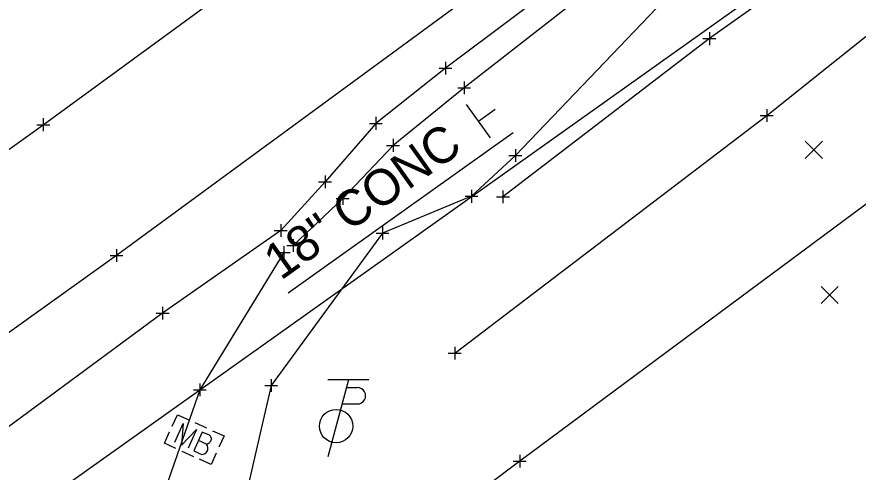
# Model space of a CAD drawing. Extents: x -4 to 139204, y -4 to 477121.
# Drawn here: x 138969.9 to 139035.5, y 476891.5 to 476927 of the extents above; entities that cross this region are included whole.
import ezdxf

# ---------------------------------------------------------------- set-up
doc = ezdxf.new("R2010")
doc.units = 0
for name, color, linetype in [('_CIVIL_CONSTRUCTION', 7, 'Continuous'), ('DR_X_Ditch', 7, 'Continuous'), ('DR_X_Storm_Sewer', 7, 'Continuous'), ('DR_X_Text', 7, 'Continuous'), ('GE_X_Alignment', 7, 'Continuous'), ('GE_X_Alignment_100_Bearings', 7, 'Continuous'), ('GE_X_Alignment_100_Cardinal_Points', 7, 'Continuous'), ('PM_X_Edge_Line', 7, 'Continuous'), ('PM_X_Surveyed_Line', 7, 'Continuous'), ('PV_X_COP', 7, 'Continuous'), ('PV_X_Driveway', 7, 'Continuous'), ('PV_X_EOP', 7, 'Continuous'), ('PV_X_Shoulder', 7, 'Continuous'), ('PV_X_Shoulder_Aggregate', 7, 'Continuous'), ('RD_X_Fence', 7, 'Continuous'), ('RW_X_Esmt_SH', 7, 'Continuous'), ('SC_Scratch1', 7, 'Continuous'), ('UT_X_Gas', 7, 'Continuous')]:
    doc.layers.add(name, color=color, linetype=linetype)

msp = doc.modelspace()

# ---------------------------------------------------------------- linework, layer by layer
at = {"layer": '_CIVIL_CONSTRUCTION'}
for p, q in [((139006.856, 476917.53), (139004.992, 476920.132)), ((139005.924, 476918.831), (139007.225, 476919.763))]:
    msp.add_line(p, q, dxfattribs=at)
at = {"layer": 'DR_X_Ditch'}
msp.add_lwpolyline([(139084.31, 476969.071), (139079.627, 476963.915), (139073.397, 476959.844), (139063.705, 476954.01), (139045.774, 476940.83), (139023.925, 476925.276), (139007.837, 476912.933)], dxfattribs=at)
at = {"layer": 'DR_X_Storm_Sewer'}
msp.add_line((138907.351, 476843.166), (139091.624, 476974.362), dxfattribs=at)
msp.add_line((138907.351, 476843.166), (139091.624, 476974.362), dxfattribs=at)
at = {"layer": 'DR_X_Text'}
msp.add_line((139008.637, 476917.918), (138991.102, 476905.433), dxfattribs=at)
msp.add_line((139008.637, 476917.918), (138991.102, 476905.433), dxfattribs=at)
at = {"layer": 'GE_X_Alignment'}
for p, q in [((139031.4, 476915.928), (139032.734, 476917.264)), ((139031.4, 476917.264), (139032.734, 476915.928)), ((139032.624, 476904.609), (139033.958, 476905.944)), ((139032.624, 476905.944), (139033.958, 476904.609))]:
    msp.add_line(p, q, dxfattribs=at)
at = {"layer": 'GE_X_Alignment_100_Bearings'}
for p, q in [((139023.925, 476925.776), (139023.925, 476924.776)), ((139023.425, 476925.276), (139024.425, 476925.276)), ((139023.925, 476925.276), (139023.925, 476925.276)), ((139002.851, 476922.965), (139003.851, 476922.965)), ((139003.351, 476923.465), (139003.351, 476922.465)), ((139003.351, 476922.965), (139003.351, 476922.965)), ((139004.817, 476921.929), (139004.817, 476920.929)), ((139004.317, 476921.429), (139005.317, 476921.429)), ((139004.817, 476921.429), (139004.817, 476921.429)), ((139028.392, 476919.779), (139028.392, 476918.779)), ((138972.007, 476919.062), (138972.007, 476918.062)), ((138972.007, 476919.062), (138972.007, 476918.062)), ((138997.924, 476919.166), (138997.924, 476918.166)), ((139027.892, 476919.279), (139028.892, 476919.279)), ((139028.392, 476919.279), (139028.392, 476919.279)), ((138971.507, 476918.562), (138972.507, 476918.562)), ((138971.507, 476918.562), (138972.507, 476918.562)), ((138972.007, 476918.562), (138972.007, 476918.562)), ((138972.007, 476918.562), (138972.007, 476918.562)), ((138997.424, 476918.666), (138998.424, 476918.666)), ((138997.924, 476918.666), (138997.924, 476918.666)), ((138999.267, 476917.449), (138999.267, 476916.449)), ((138998.767, 476916.949), (138999.767, 476916.949)), ((138999.267, 476916.949), (138999.267, 476916.949)), ((139008.806, 476916.658), (139008.806, 476915.658)), ((139008.306, 476916.158), (139009.306, 476916.158)), ((139008.806, 476916.158), (139008.806, 476916.158)), ((138993.965, 476914.598), (138993.965, 476913.598)), ((138993.465, 476914.098), (138994.465, 476914.098)), ((138993.965, 476914.098), (138993.965, 476914.098)), ((138995.343, 476913.315), (138995.343, 476912.315)), ((139005.384, 476913.478), (139005.384, 476912.478)), ((139007.837, 476913.433), (139007.837, 476912.433)), ((138994.843, 476912.815), (138995.843, 476912.815)), ((138995.343, 476912.815), (138995.343, 476912.815)), ((139004.884, 476912.978), (139005.884, 476912.978)), ((139005.384, 476912.978), (139005.384, 476912.978)), ((139007.337, 476912.933), (139008.337, 476912.933)), ((139007.837, 476912.933), (139007.837, 476912.933)), ((138990.512, 476910.809), (138990.512, 476909.809)), ((138998.45, 476910.612), (138998.45, 476909.612)), ((138990.012, 476910.309), (138991.012, 476910.309)), ((138990.512, 476910.309), (138990.512, 476910.309)), ((138997.95, 476910.112), (138998.95, 476910.112)), ((138998.45, 476910.112), (138998.45, 476910.112)), ((138990.994, 476909.144), (138991.994, 476909.144)), ((138991.494, 476909.644), (138991.494, 476908.644)), ((138991.494, 476909.144), (138991.494, 476909.144)), ((138977.717, 476908.855), (138977.717, 476907.855)), ((138977.717, 476908.855), (138977.717, 476907.855)), ((138990.254, 476908.584), (138991.254, 476908.584)), ((138990.754, 476909.084), (138990.754, 476908.084)), ((138990.754, 476908.584), (138990.754, 476908.584)), ((138977.217, 476908.355), (138978.217, 476908.355)), ((138977.217, 476908.355), (138978.217, 476908.355)), ((138977.717, 476908.355), (138977.717, 476908.355)), ((138977.717, 476908.355), (138977.717, 476908.355)), ((138981.306, 476904.356), (138981.306, 476903.356)), ((138980.806, 476903.856), (138981.806, 476903.856)), ((138981.306, 476903.856), (138981.306, 476903.856)), ((139003.575, 476900.734), (139004.575, 476900.734)), ((139004.075, 476901.234), (139004.075, 476900.234)), ((139004.075, 476900.734), (139004.075, 476900.734)), ((138989.767, 476898.719), (138989.767, 476897.719)), ((138984.215, 476898.385), (138984.215, 476897.385)), ((138989.267, 476898.219), (138990.267, 476898.219)), ((138989.767, 476898.219), (138989.767, 476898.219)), ((138983.715, 476897.885), (138984.715, 476897.885)), ((138984.215, 476897.885), (138984.215, 476897.885)), ((139009.14, 476892.822), (139009.14, 476891.822)), ((139008.64, 476892.322), (139009.64, 476892.322)), ((139009.14, 476892.322), (139009.14, 476892.322))]:
    msp.add_line(p, q, dxfattribs=at)
at = {"layer": 'GE_X_Alignment_100_Cardinal_Points'}
for p, q in [((138995.792, 476898.652), (138994.186, 476892.652)), ((138997.392, 476898.652), (138994.192, 476898.652)), ((138995.632, 476898.052), (138996.482, 476898.052)), ((138995.291, 476896.777), (138996.482, 476896.777))]:
    msp.add_line(p, q, dxfattribs=at)
msp.add_circle((138994.829, 476895.052), 1.3, dxfattribs=at)
msp.add_arc((138996.495, 476897.414), 0.638, 268.8767, 91.1233, dxfattribs=at)
at = {"layer": 'PM_X_Edge_Line'}
msp.add_lwpolyline([(139119.978, 477018.535), (139108.07, 477008.289), (139096.43, 476998.562), (139075.62, 476981.789), (139057.894, 476968.012), (139018.116, 476938.023), (138977.717, 476908.355), (138952.937, 476890.592), (138936.689, 476878.892)], dxfattribs=at)
at = {"layer": 'PM_X_Surveyed_Line'}
msp.add_lwpolyline([(138930.184, 476888.564), (138972.007, 476918.562), (139012.493, 476948.198), (139029.811, 476961.233), (139052.078, 476978.039), (139073.558, 476995.35), (139089.175, 477007.916), (139110.846, 477026.03), (139111.346, 477026.745)], dxfattribs=at)
at = {"layer": 'PV_X_COP'}
msp.add_lwpolyline([(138930.195, 476888.554), (138972.007, 476918.562), (139012.493, 476948.198), (139029.811, 476961.233), (139052.078, 476978.039), (139073.558, 476995.35), (139089.175, 477007.916), (139110.846, 477026.03), (139129.377, 477042.526), (139155.719, 477066.268), (139171.584, 477080.905)], dxfattribs=at)
at = {"layer": 'PV_X_Driveway'}
msp.add_lwpolyline([(138990.754, 476908.584), (138984.215, 476897.885), (138980.48, 476887.146), (138978.866, 476875.029), (138979.368, 476856.937)], dxfattribs=at)
at = {"layer": 'PV_X_EOP'}
msp.add_lwpolyline([(139119.987, 477018.511), (139108.07, 477008.289), (139096.43, 476998.562), (139075.62, 476981.789), (139057.894, 476968.012), (139018.116, 476938.023), (138977.717, 476908.355), (138952.937, 476890.592), (138936.542, 476879.008)], dxfattribs=at)
at = {"layer": 'PV_X_Shoulder'}
msp.add_lwpolyline([(139183.638, 477072.424), (139153.919, 477045.299), (139136.787, 477030.023), (139126.343, 477020.832), (139109.649, 477006.831), (139097.905, 476996.885), (139077.102, 476979.89), (139059.387, 476965.891), (139020.106, 476935.561), (139003.351, 476922.965), (138997.924, 476918.666), (138993.965, 476914.098), (138990.512, 476910.309), (138981.306, 476903.856), (138956.564, 476885.614), (138940.343, 476873.773)], dxfattribs=at)
at = {"layer": 'PV_X_Shoulder_Aggregate'}
msp.add_lwpolyline([(139124.206, 477016.86), (139110.781, 477005.495), (139098.924, 476995.454), (139078.061, 476978.654), (139060.667, 476964.123), (139021.044, 476934.127), (139004.817, 476921.429), (138999.267, 476916.949), (138995.343, 476912.815), (138991.494, 476909.144)], dxfattribs=at)
at = {"layer": 'RD_X_Fence'}
msp.add_lwpolyline([(139170.211, 476966.83), (139152.176, 476981.457), (139140.024, 476988.541), (139126.511, 476979.248), (139077.418, 476943.213), (139054.3, 476926.021), (139036.036, 476912.286), (139009.14, 476892.322), (138983.005, 476872.624), (138984.167, 476847.153), (138984.924, 476831.748)], dxfattribs=at)
at = {"layer": 'RW_X_Esmt_SH'}
for p, q in [((138983.811, 476895.322), (138984.723, 476894.907)), ((138983.771, 476893.998), (138983.771, 476893.998)), ((138982.799, 476893.098), (138983.711, 476892.683))]:
    msp.add_line(p, q, dxfattribs=at)
for points in [[(138982.055, 476895.055), (138982.456, 476895.938), (138983.339, 476895.537)], [(138982.26, 476893.807), (138982.922, 476895.263), (138982.787, 476893.567), (138983.954, 476894.794), (138983.292, 476893.337)], [(138982.328, 476893.313), (138981.445, 476893.714), (138981.846, 476894.597)], [(138984.73, 476893.638), (138984.813, 476893.669), (138984.863, 476893.688), (138984.902, 476893.712), (138984.924, 476893.73), (138984.967, 476893.765), (138984.995, 476893.794), (138985.054, 476893.864), (138985.07, 476893.899), (138985.091, 476893.944), (138985.11, 476894.018), (138985.113, 476894.086), (138985.1, 476894.148), (138985.063, 476894.22), (138985.028, 476894.263), (138985.01, 476894.285), (138984.964, 476894.334), (138984.402, 476894.59), (138983.739, 476893.134), (138984.37, 476892.847), (138984.471, 476892.856), (138984.566, 476892.882), (138984.665, 476892.948), (138984.746, 476893.035), (138984.805, 476893.133), (138984.836, 476893.202), (138984.844, 476893.281), (138984.845, 476893.405), (138984.819, 476893.5), (138984.73, 476893.638), (138984.099, 476893.925)], [(138985.193, 476894.693), (138986.097, 476894.282), (138985.696, 476893.399)], [(138985.487, 476892.941), (138985.086, 476892.058), (138984.181, 476892.469)]]:
    msp.add_lwpolyline(points, dxfattribs=at)
at = {"layer": 'SC_Scratch1'}
msp.add_lwpolyline([(139071.871, 476964.685), (139042.717, 476944.31), (139020.962, 476928.905), (139008.806, 476916.158), (139005.384, 476912.978), (138998.45, 476910.112), (138989.767, 476898.219), (138984.604, 476875.789)], dxfattribs=at)
at = {"layer": 'UT_X_Gas'}
msp.add_lwpolyline([(139004.075, 476900.734), (139028.392, 476919.279), (139049.353, 476936.04), (139135.72, 476993.765), (139150.82, 477005.632), (139162.46, 477015.27), (139171.782, 477023.038), (139186.18, 477034.164), (139199.281, 477045.473), (139201.496, 477047.37), (139194.822, 477055.784), (139186.687, 477066.39), (139182.688, 477071.332), (139173.257, 477082.641), (139163.808, 477093.452), (139160.449, 477097.743)], dxfattribs=at)

# ---------------------------------------------------------------- texts
at = {"layer": 'DR_X_Text'}
msp.add_text('18" CONC', height=2.8, rotation=35.44955, dxfattribs=at).set_placement((138990.516, 476906.368))
msp.add_text('18" CONC', height=2.8, rotation=35.44955, dxfattribs=at).set_placement((138990.516, 476906.368))

doc.saveas('drawing.dxf')
